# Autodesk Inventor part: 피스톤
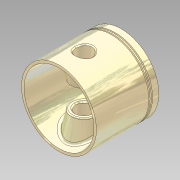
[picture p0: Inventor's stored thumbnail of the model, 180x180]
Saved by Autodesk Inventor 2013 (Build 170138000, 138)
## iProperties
Manager: KYOUNG IL JANG
Company: 한국ATC센터
Created: 2012-10
Part Number: 피스톤
Document SubType Name: Modeling
Density: 1 g/cm^3
Checked By: KYOUNG IL JANG
Vendor: CBT Solutions
Designer: KYOUNG IL JANG
Material: 일반
Author: KYOUNG IL JANG
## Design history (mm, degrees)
sketch "스케치1"
  geometry: L1 (0, 0)-(0, 50); L2 (0, 50)-(30, 50); L3 (30, 50)-(30, 45); L4 (30, 45)-(28, 45); L5 (28, 45)-(28, 44); L6 (28, 44)-(30, 44); L7 (30, 44)-(30, 43); L8 (30, 43)-(28, 43); L9 (28, 43)-(28, 42); L10 (28, 42)-(30, 42); L11 (30, 42)-(30, 0); L12 (30, 0)-(28, 0); L13 (28, 0)-(23, 45); L14 (23, 45)-(0, 45)
  constraints: 28 end point, 10 parallel, 5 collinear, 2 perpendicular, 2 point on line, 1 vertical
  dimensions: "d0" = 50 distance of L1.start L1.end; "d1" = 60 diameter of L3 L1; "d2" = 5 distance between parallel lines of L2 L14; "d3" = 2 distance of L11.end L12.end; "d5" = 5 distance of L2.end L3.end; "d6" = 1 distance of L4.end L5.end; "d7" = 2 distance of L9.end L10.end; "d26" = 46 diameter of L13.end L1
revolve "회전1" sketch "스케치1" stored, may be unused: angle "d8" = 90 deg
node "작업 평면1"
sketch "스케치2"
  geometry: L1 (-28, 0)-(28, 0) reference; C1 r 10 at (0, 20); C2 r 6.5 at (0, 20); 1 further point
  constraints: 2 centre point, 1 coincident, 1 vertical alignment
  dimensions: "d10" = 20 diameter of C1; "d13" = 20 distance from line of C1.centre L1; "d14" = 13 diameter of C2
extrude "돌출1" join sketch "스케치2" stored distance "d11" = 10; taper "d12" = 12 deg
extrude "돌출2" cut sketch "스케치2" stored distance "d15" = 10; taper "d16" = 0 deg
fillet "모깎기1" dims "d17" = 2, "d21" = 3
chamfer "모따기1" distance "d18" = 1; stored, may be unused: second distance "d19" = 2, angle "d20" = 45 deg
chamfer "모따기2" distance "d22" = 1; stored, may be unused: second distance "d23" = 2, angle "d24" = 45 deg
fillet "모깎기2" dims "d25" = 1
node "솔리드1"
mirror "대칭1"
